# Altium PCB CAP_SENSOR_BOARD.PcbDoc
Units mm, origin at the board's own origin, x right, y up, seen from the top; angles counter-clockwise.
Board outline 114.3 x 63.5 mm, 4 copper layers (Top Layer, GND, PWR, Bottom Layer), stack 1.591 mm thick; 54 components, 40 nets, 232 pads, 121 vias.
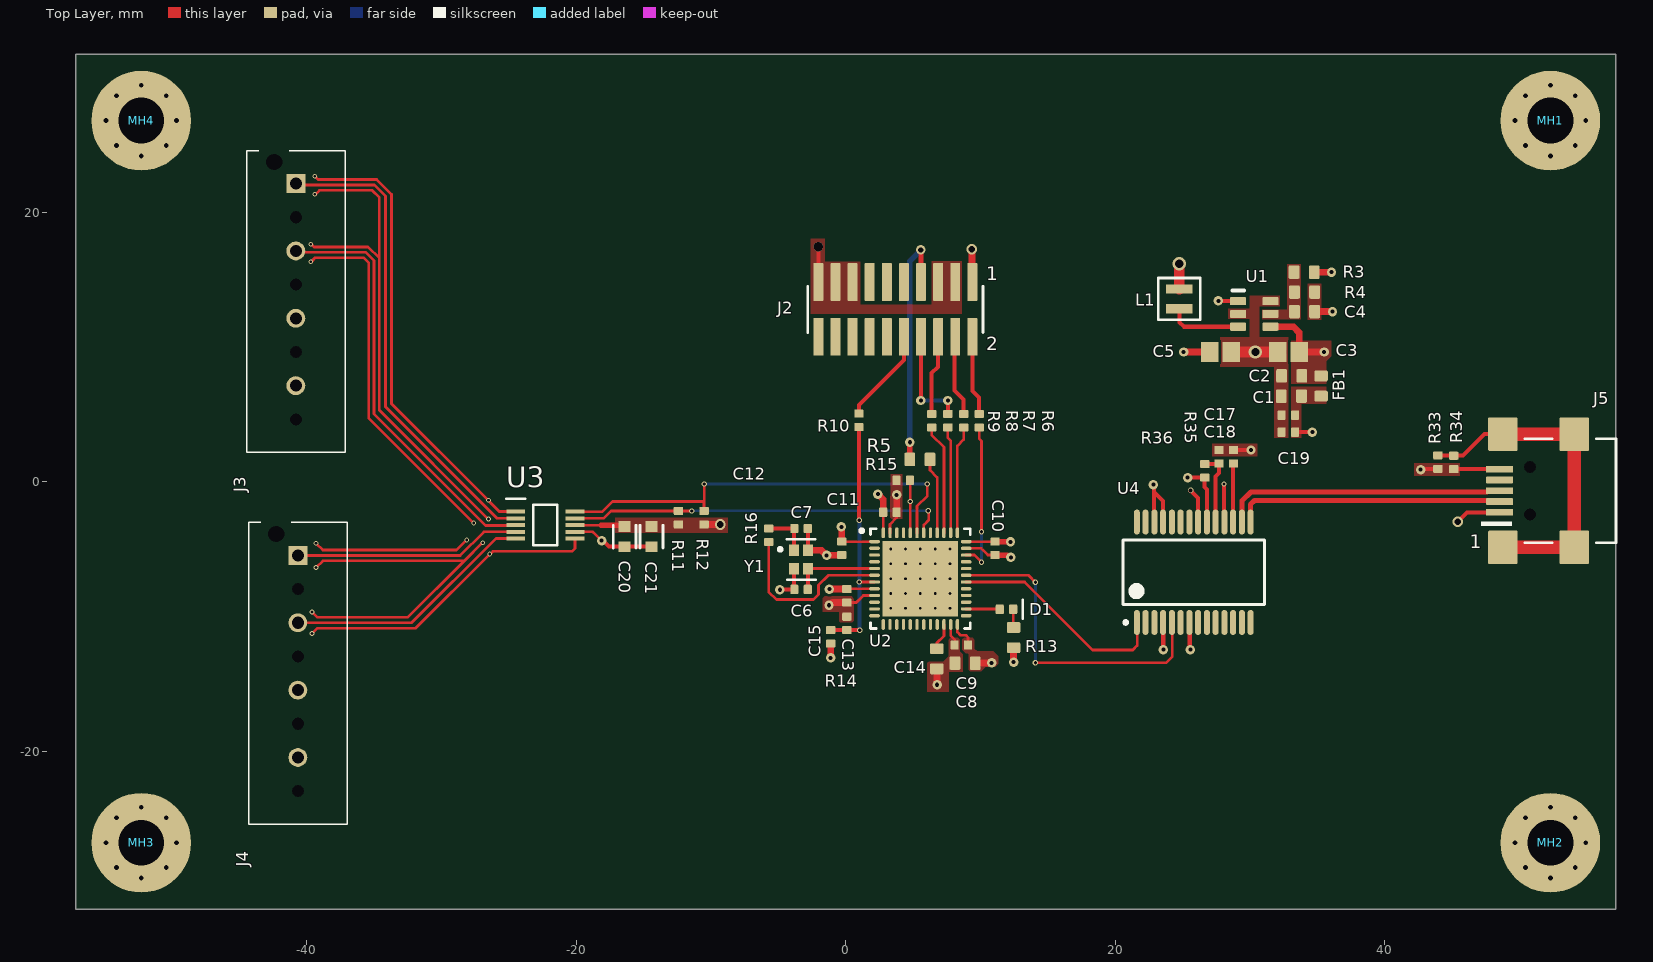
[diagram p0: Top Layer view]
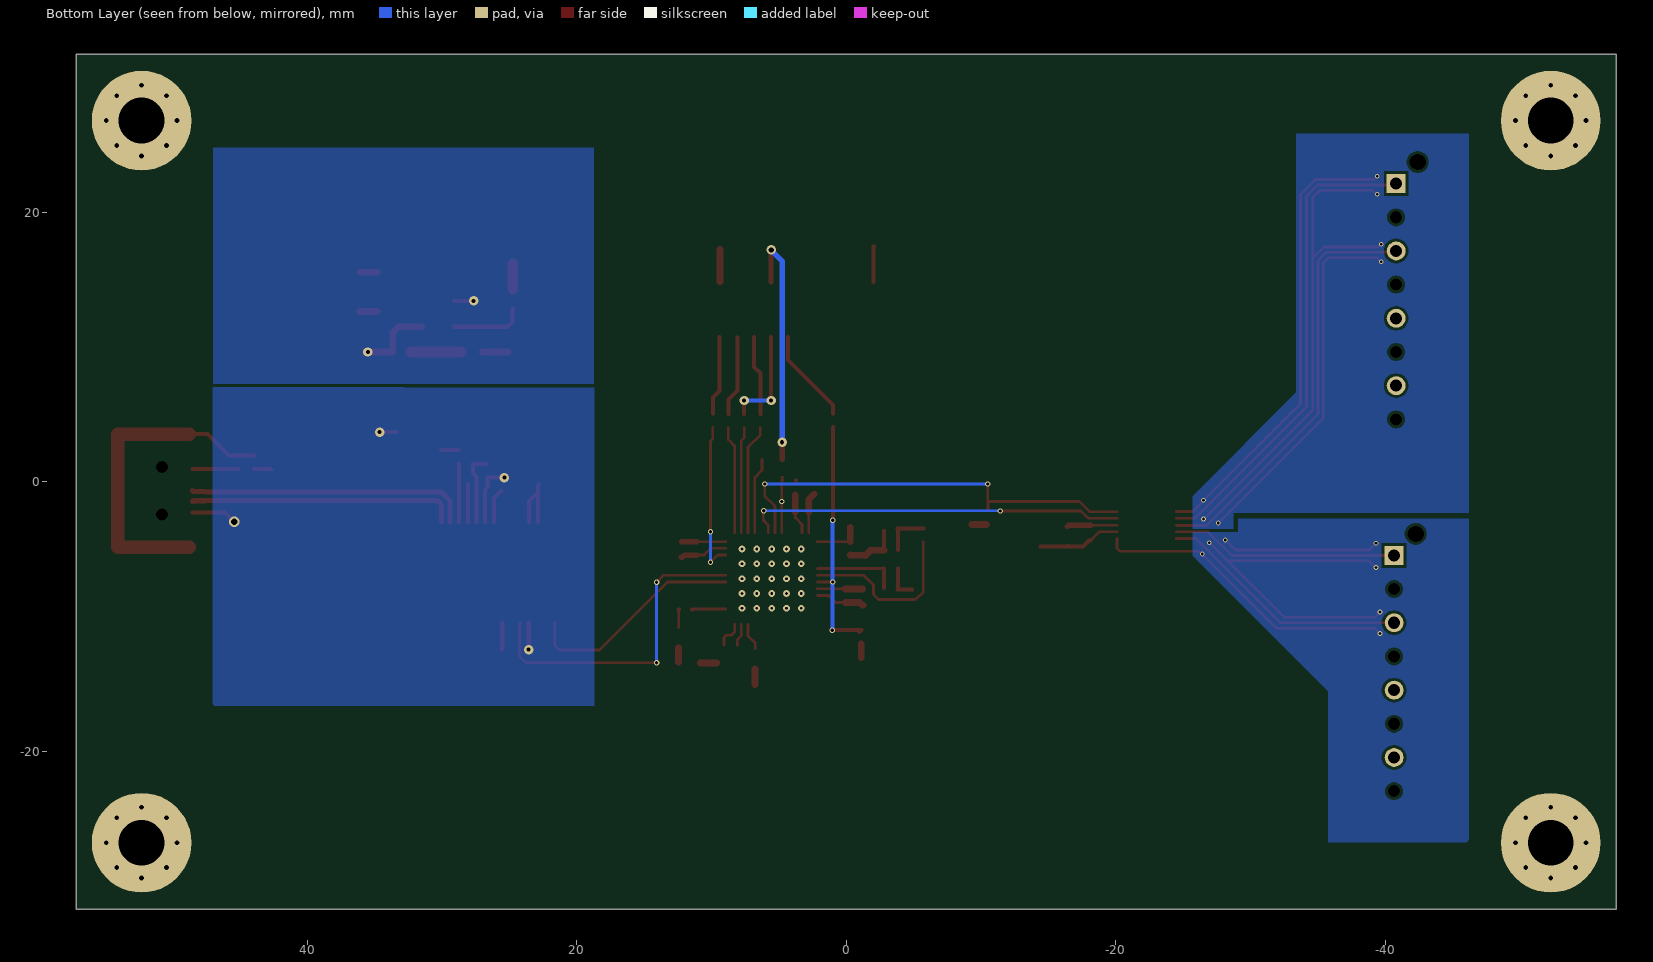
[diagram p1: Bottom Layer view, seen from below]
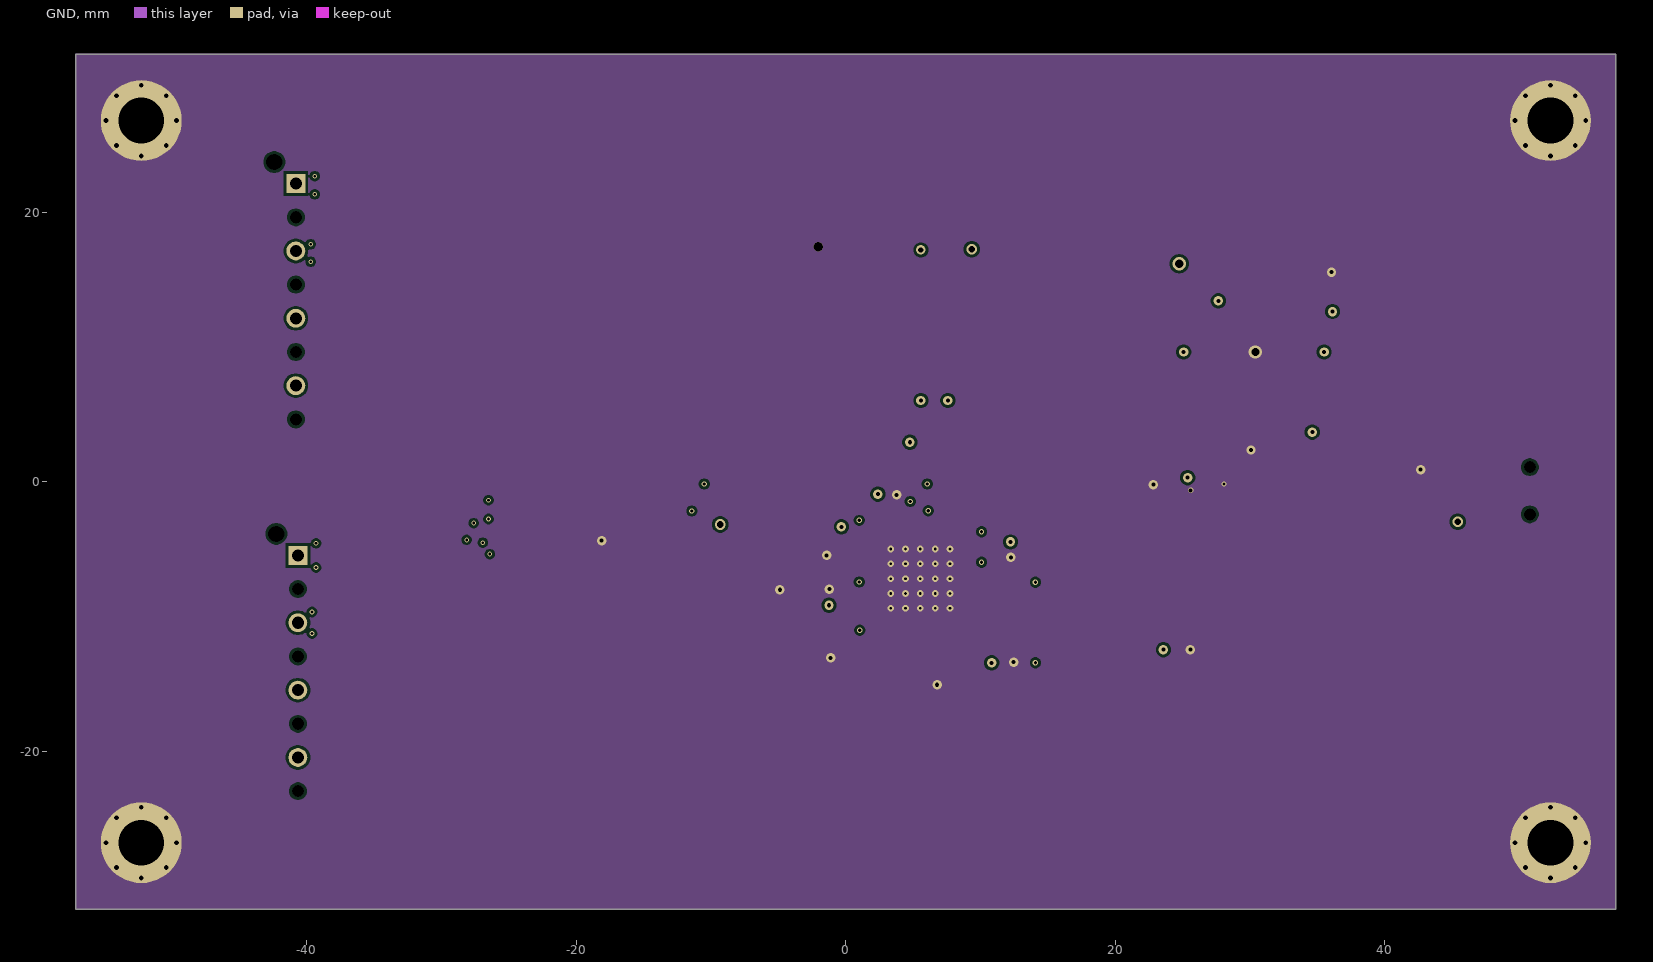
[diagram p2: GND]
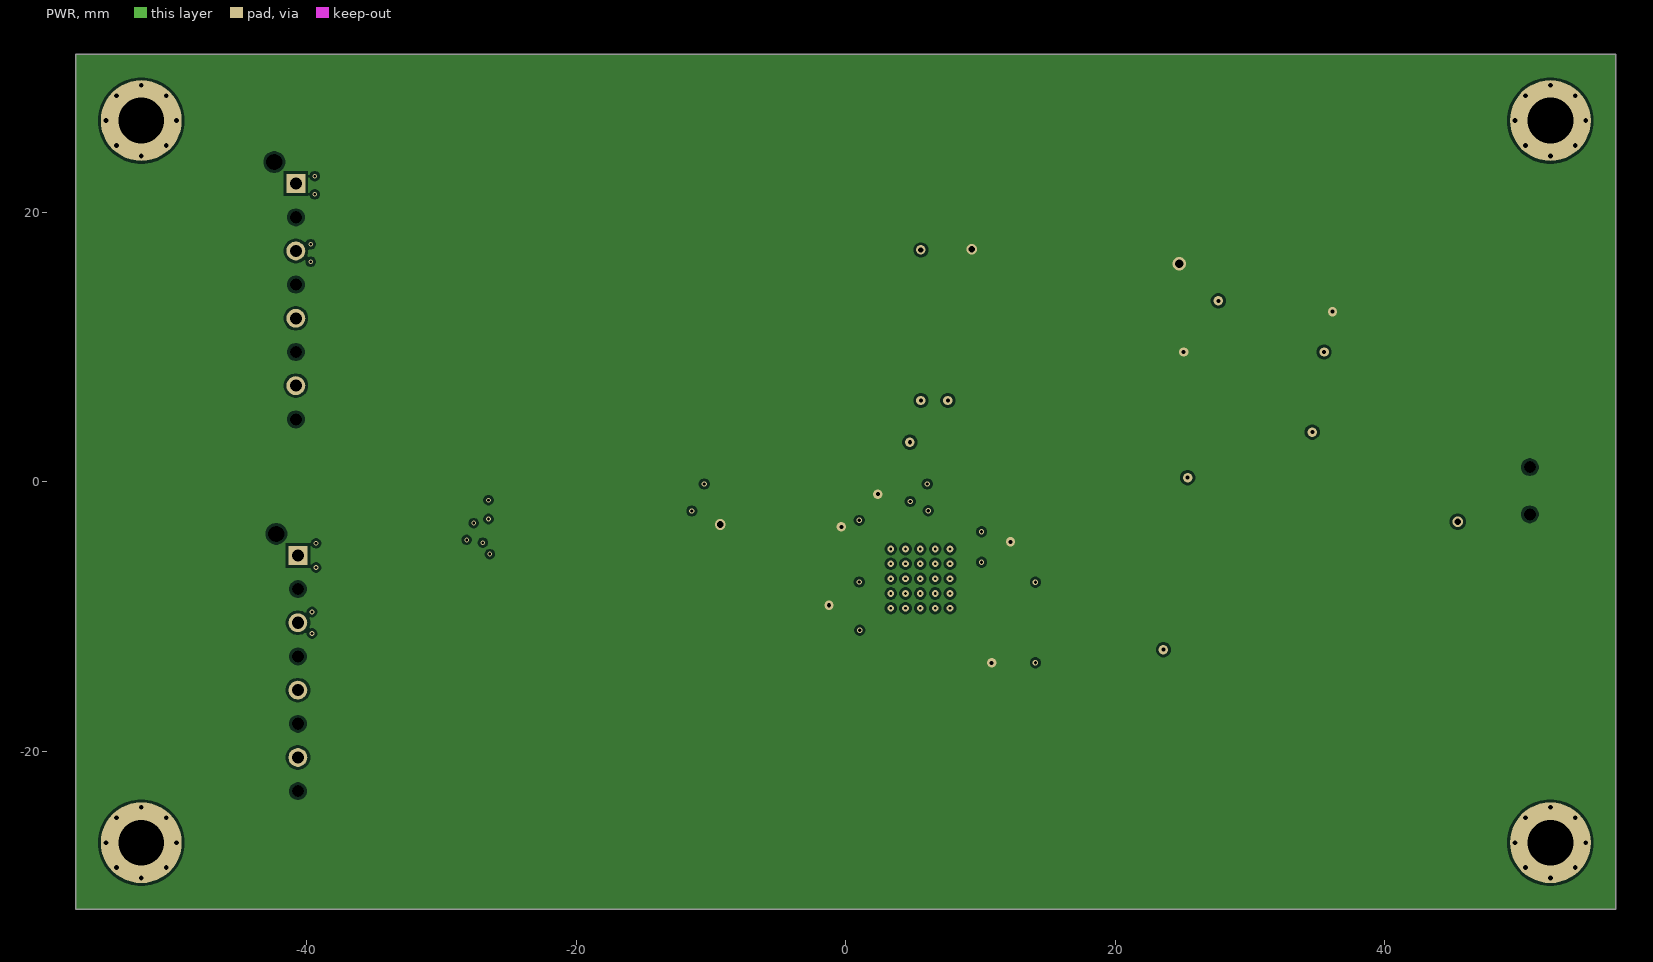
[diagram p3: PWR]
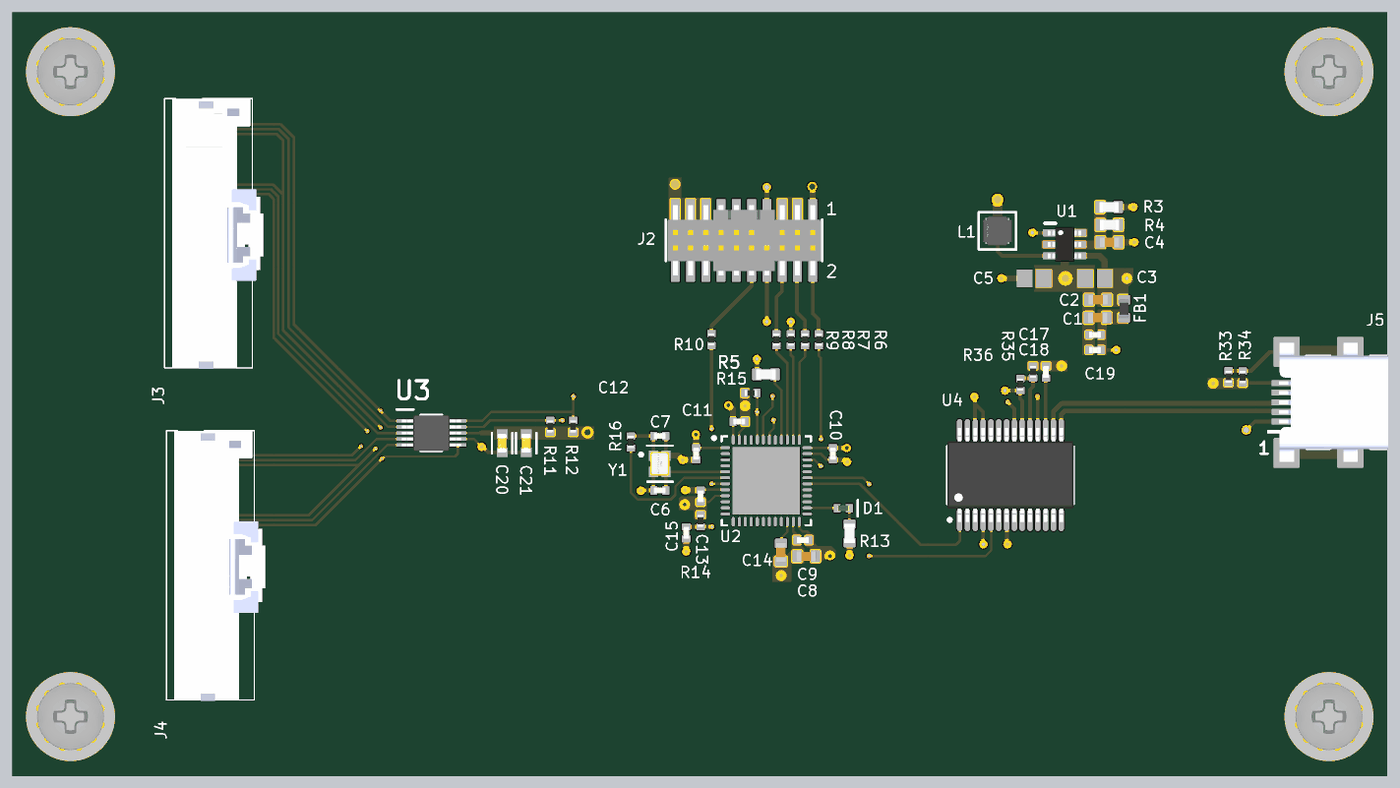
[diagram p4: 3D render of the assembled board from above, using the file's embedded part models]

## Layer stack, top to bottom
Top Solder: solder mask 0.0254, SM-001, Dk 4
Top Layer: signal copper 0.035
Dielectric 1: prepreg 0.2104, PP-7628, Dk 4.4
GND: signal copper 0.0175
Dielectric 3: core 1.065, Core-039, Dk 4.6
PWR: signal copper 0.0175
Dielectric 5: prepreg 0.2104, PP-7628, Dk 4.4
Bottom Layer: signal copper 0.035
Bottom Solder: solder mask 0.0254, SM-001, Dk 4

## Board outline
-57.15,-31.755 -57.15,31.745 57.15,31.745 57.15,-31.755

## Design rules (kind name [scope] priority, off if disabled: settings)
Clearance [All] p1: gap=0.2 ignorepadtopadclearanceinfootprint=FALSE
DiffPairsRouting [All] p1: maxlimit=0.254 minlimit=0.254 mostfreqgap=0.254 toplayer_minwidth=0.381 toplayer_maxwidth=0.381 toplayer_prefwidth=0.381 midlayer1_minwidth=0.381 midlayer1_maxwidth=0.381 midlayer1_prefwidth=0.381 midlayer2_minwidth=0.381 midlayer2_maxwidth=0.381 midlayer2_prefwidth=0.381 bottomlayer_minwidth=0.381 bottomlayer_maxwidth=0.381 bottomlayer_prefwidth=0.381 maxuncoupledlength=12.7
HoleSize [All] p1: absolutevalues=TRUE maxlimit=4 minlimit=0.025 maxpercent=80.000 minpercent=20.000
MinimumSolderMaskSliver [All] p1: minsoldermaskwidth=0.1
PolygonConnect [All] p1: connectstyle=Direct reliefconductorwidth=0.254 reliefentries=4 polygonreliefangle="90 Angle" airgapwidth=0.254
RoutingVias [All] p1: holewidth=0.7 width=0.3 viastyle="Through Hole" minholewidth=0.15 minwidth=0.2 maxholewidth=0.711 maxwidth=1.27
SolderMaskExpansion [All] p1: expansion=0.102 istentingtop=FALSE
UnRoutedNet [All] p1: checkbadconnections=TRUE
Width [All] p1: maxlimit=1 minlimit=0.2 preferedwidth=0.3 midlayer1_maxwidth=1 midlayer2_maxwidth=1 bottomlayer_maxwidth=1 minimp=50.000000 maximp=50.000000 favimp=50.000000
26 further rules are at their usual default settings.

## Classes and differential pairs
component class 5_UART: C17 C18 C19 J5 R33 R34 R35 R36 U4
component class 3_PERIPHERAL: C20 C21 J3 J4 U3
component class 2_MCU: C6 C7 C8 C9 C10 C11 C12 C13 C14 C15 D1 J2 R5 R6 R7 R8 R9 R10 R11 R12 R13 R14 R15 R16 U2 Y1
component class 1_POWER: C1 C2 C3 C4 C5 FB1 L1 MH1 MH2 MH3 MH4 R3 R4 U1
differential pair USB: +USB_P -USB_N

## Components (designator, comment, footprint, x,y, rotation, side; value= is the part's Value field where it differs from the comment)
C1 "100n" CAP_0603 33.075,6.35 r0 top
C2 "100n" CAP_0603 33.1,7.85 r0 top
C3 "4.7uF" CAPC2013X140X50NL20T25 32.85,9.625 r0 top
C4 "22p" CAP_0603 34.05,12.625 r0 top
C5 "4.7uF" CAPC2013X140X50NL20T25 27.8,9.625 r180 top
C6 "6pF" CAP_0402#1 -3.325,-8 r180 top
C7 "6pF" CAP_0402#1 -3.325,-3.475 r0 top
C8 "2.2uF" CAP_0603 8.85,-13.475 r0 top
C9 "100nF" CAP_0402#1 8.575,-12.125 r0 top
C10 "100nF" CAP_0402#1 11.075,-4.95 r90 top
C11 "100nF" CAP_0402#1 3.275,-2.275 r180 top
C12 "100nF" CAP_0402#1 -0.3,-4.95 r90 top
C13 "100nF" CAP_0402#1 0.075,-8.475 r270 top
C14 "2.2uF" CAP_0603 6.75,-13.15 r90 top
C15 "2.2uF" CAP_0402#1 -1.125,-11.525 r90 top
C17 "1uF" CAP_0402#2 32.85,4.937 r180 top
C18 "0.1uF" CAP_0402#2 32.85,3.675 r180 top
C19 "100nF" CAP_0402#1 28.775,1.85 r270 top
C20 "0.1uF" FP-CC0603-DA-MFG -16.425,-4.075 r270 top value="100 nF"
C21 "1uF" FP-CC0603-DA-MFG -14.425,-4.075 r270 top value="1 uF"
D1 "GREEN" LED_0402_GREEN 11.925,-9.475 r0 top
FB1 "120R" FB_0603 35.275,7.1 r90 top
J2 "CN_20P_FTSH-110-01-F-DV-007-K" CN_20P_FTSH-110-01-F-DV-007-K 3.677,12.785 r180 top
J3 "207843-0008" CN_8P_2078430008 -40.825,22.125 r90 top
J4 "207843-0008" CN_8P_2078430008 -40.675,-5.475 r90 top
J5 "CN_5P_USB_UX60-MB-5ST" CN_5P_UX60-MB-5ST 52.675,-0.675 r90 top
L1 "10u" FP-NRH2412-MFG 24.75,13.575 r90 top
MH1 "M3-PTH" MTG_M3_PTH_90317A112 52.3,26.8 r0 top
MH2 "M3-PTH" MTG_M3_PTH_90317A112 52.3,-26.8 r0 top
MH3 "M3-PTH" MTG_M3_PTH_90317A112 -52.3,-26.8 r0 top
MH4 "M3-PTH" MTG_M3_PTH_90317A112 -52.3,26.8 r0 top
R3 "280k" RES_0603 34.025,15.55 r0 top
R4 "887k" RES_0603 34.05,14.075 r0 top
R5 "DNI" RES_0603 5.5,1.65 r0 top
R6 "100R" RES_0402 9.9,4.525 r270 top
R7 "100R" RES_0402 8.75,4.525 r270 top
R8 "100R" RES_0402 6.375,4.525 r270 top
R9 "100R" RES_0402 7.575,4.525 r270 top
R10 "100R" RES_0402 0.975,4.55 r270 top
R11 "2.2K" RES_0402 -12.425,-2.675 r270 top
R12 "2.2k" RES_0402 -10.525,-2.675 r270 top
R13 "1k" RES_0603 12.45,-11.575 r270 top
R14 "10k" RES_0402 0.075,-10.525 r90 top
R15 "10k" RES_0402 4.25,0.1 r0 top
R16 "0R" RES_0402 -5.725,-3.975 r270 top
R33 "0R" RES_0402 43.95,1.45 r90 top
R34 "0R" RES_0402 45.125,1.425 r90 top
R35 "5.1k" RES_0402 26.65,0.8 r270 top
R36 "10k" RES_0402 27.7,1.85 r270 top
U1 "LTC3405ES6#TRMPBF" SOT-23-6 30.32,12.45 r270 top
U2 "STM32F411CEU6" STM-UFQFPN48_L 5.532,-7.199 r0 top
U3 "FDC1004QDGSRQ1" SOP50P490X110-10N -22.3,-3.225 r0 top
U4 "FT232RL" FTDI-SSOP-28_M 25.825,-6.725 r90 top
Y1 "24Mhz" FP-ECX-1637-MFG -3.325,-5.775 r270 top

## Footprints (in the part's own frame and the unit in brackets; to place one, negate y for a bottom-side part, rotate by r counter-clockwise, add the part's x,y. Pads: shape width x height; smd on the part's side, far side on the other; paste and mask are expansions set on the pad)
CAP_0402#1 [mm]
  rrect25% 0.6x0.7 smd: 1(-0.5,0) 2(0.5,0)
  body extent -0.5,-0.26 0.5,0.26, height 0.37
CAP_0402#2 [mm]
  rrect25% 0.6x0.7 smd mask+0.08: 1(-0.5,0) 2(0.5,0)
  body extent -0.5,-0.26 0.5,0.26, height 0.37
CAP_0603 [mm]
  rrect25% 0.8x1 smd: 1(-0.75,0) 2(0.75,0)
  body extent -0.8,-0.4 0.8,0.4, height 0.51
CAPC2013X140X50NL20T25 [mm] "Chip Capacitor, 2-Leads, Body 2.00x1.25mm, IPC Medium Density"
  rect 1.3x1.45 smd mask+0.06: 1(-0.8,0) 2(0.8,0)
  body extent -1.1,-0.72 1.1,0.72, height 1.4
CN_5P_UX60-MB-5ST [mm]
  round 0.5 hole 0.9 unplated paste-2539.97 mask+0.35: 0(-1.75,1.9) 0(1.75,1.9)
  rrect20% 0.5x2 smd paste+0 mask+0: 1(-1.6,4.15) 2(-0.8,4.15) 3(0,4.15) 4(0.8,4.15) 5(1.6,4.15)
  rrect10% 2.5x2.2 smd paste+0 mask+0: 6(-4.2,3.9) 7(4.2,3.9) 8(-4.2,-1.4) 9(4.2,-1.4)
  Top Layer pour cut-out: -3.85,-4.5 -3.85,-2.525 -3.05,-2.525 -3.026,-2.523 -2.981,-2.504 -2.946,-2.469 -2.927,-2.424 -2.925,-2.4 -2.925,-2.4 -2.925,-0.4 -2.927,-0.376 -2.946,-0.331 -2.981,-0.296 -3.026,-0.277 -3.05,-0.275 -3.05,-0.275 -3.85,-0.275 -3.85,1.9 -1.75,1.9 -1.75,3.125 1.75,3.125 1.75,1.9 3.85,1.9 3.85,-0.275 3.05,-0.275 3.026,-0.277 2.981,-0.296 2.946,-0.331 2.927,-0.376 2.925,-0.4 2.925,-0.4 2.925,-2.4 2.927,-2.424 2.946,-2.469 2.981,-2.504 3.026,-2.523 3.05,-2.525 3.05,-2.525 3.85,-2.525 3.85,-4.5
  silkscreen extent -3.85,-4.5 3.85,5.5, body extent -4.95,-4.53 4.95,4.53, height 3.95
CN_8P_2078430008 [mm]
  rect 1.4x1.4 hole 0.9: 1(0,0)
  round 0 hole 0.9: 2(-2.5,0) 4(-7.5,0) 6(-12.5,0) 8(-17.5,0)
  round 1.4 hole 0.9: 3(-5,0) 5(-10,0) 7(-15,0)
  round 0.6 hole 1.2 unplated: MH1(1.6,1.6)
  silkscreen extent -19.95,-3.65 2.45,3.65, body extent -20.01,-4.56 2.44,3.03, height 11.97
CN_20P_FTSH-110-01-F-DV-007-K [mm] "Connector, Header, 20 Pos, 0.05\" Pitch, Vertical, Keyed, SM"
  rrect10% 0.74x2.79 smd: 1(-5.715,-2.035) 2(-5.715,2.035) 3(-4.445,-2.035) 4(-4.445,2.035) 5(-3.175,-2.035) 6(-3.175,2.035) 7(-1.905,-2.035) 8(-1.905,2.035) 9(-0.635,-2.035) 10(-0.635,2.035) 11(0.635,-2.035) 12(0.635,2.035) 13(1.905,-2.035) 14(1.905,2.035) 15(3.175,-2.035) 16(3.175,2.035) 17(4.445,-2.035) 18(4.445,2.035) 19(5.715,-2.035) 20(5.715,2.035)
  silkscreen extent -6.5,-1.72 6.5,1.72, body extent -6.35,-2.92 6.35,2.92, height 6.16
FB_0603 [mm]
  rrect25% 0.8x1 smd: 1(-0.75,0) 2(0.75,0)
  body extent -0.8,-0.4 0.8,0.4, height 0.81
FP-CC0603-DA-MFG [mm]
  rect 0.8x0.9 smd paste+0 mask+0: 1(-0.75,0) 2(0.75,0)
  silkscreen extent -0.85,-0.85 0.85,0.85, body extent -1.35,-0.75 1.35,0.75, height 0.25
FP-ECX-1637-MFG [mm]
  rect 0.85x0.75 smd paste+0 mask+0: 1(-0.675,-0.525) 2(0.675,-0.525) 3(0.675,0.525) 4(-0.675,0.525)
  silkscreen extent -1.5,-1.67 1.5,1.07, body extent -1.2,-1 1.2,1, height 0.25
FP-NRH2412-MFG [mm]
  rect 0.7x2 smd paste+0 mask+0: 1(-0.725,0) 2(0.725,0)
  silkscreen extent -1.55,-1.55 1.55,1.55, body extent -1.35,-1.35 1.35,1.35, height 0.25
FTDI-SSOP-28_M [mm] "SOP, 28-Leads, Body 10.5x5.6mm, Pitch 0.65mm, IPC Low Density"
  oval 1.85x0.45 smd: 1(-3.725,4.225) 2(-3.725,3.575) 3(-3.725,2.925) 4(-3.725,2.275) 5(-3.725,1.625) 6(-3.725,0.975) 7(-3.725,0.325) 8(-3.725,-0.325) 9(-3.725,-0.975) 10(-3.725,-1.625) 11(-3.725,-2.275) 12(-3.725,-2.925) 13(-3.725,-3.575) 14(-3.725,-4.225) 15(3.725,-4.225) 16(3.725,-3.575) 17(3.725,-2.925) 18(3.725,-2.275) 19(3.725,-1.625) 20(3.725,-0.975) 21(3.725,-0.325) 22(3.725,0.325) 23(3.725,0.975) 24(3.725,1.625) 25(3.725,2.275) 26(3.725,2.925) 27(3.725,3.575) 28(3.725,4.225)
  silkscreen extent -3.85,-5.25 2.4,5.25, body extent -3.9,-5.25 3.9,5.25, height 2
LED_0402_GREEN [mm]
  rrect25% 0.6x0.7 smd: A(-0.5,0) K(0.5,0)
  silkscreen extent 1.2,-0.7 1.2,0.7, body extent -0.51,-0.25 0.51,0.25, height 0.45
MTG_M3_PTH_90317A112 [mm] "M3 W INTERNAL TOOTH LOCK WASHER 90317A112"
  round 7.4 / inner round 6 / far side round 7.4 hole 3.404 paste-2539.97 mask+0: 1(0,0)
  body extent -3.7,-3.7 3.7,3.7, height 2.92
RES_0402 [mm]
  rrect25% 0.6x0.7 smd: 1(-0.5,0) 2(0.5,0)
  body extent -0.5,-0.25 0.5,0.25, height 0.3
RES_0603 [mm]
  rrect25% 0.8x1 smd: 1(-0.75,0) 2(0.75,0)
  body extent -0.8,-0.43 0.8,0.43, height 0.52
SOP50P490X110-10N [mm]
  rect 1.4x0.3 smd mask+0.05: 1(-2.2,1) 2(-2.2,0.5) 3(-2.2,0) 4(-2.2,-0.5) 5(-2.2,-1) 6(2.2,-1) 7(2.2,-0.5) 8(2.2,0) 9(2.2,0.5) 10(2.2,1)
  silkscreen extent -2.9,-1.5 0.87,1.95, body extent -2.46,-1.5 2.46,1.5, height 1.1
SOT-23-6 [mm]
  rrect25% 0.6x1.2 smd mask+0.04: 1(-0.95,-1.2) 2(0,-1.2) 3(0.95,-1.2) 4(0.95,1.2) 5(0,1.2) 6(-0.95,1.2)
  silkscreen extent -1.75,-1.63 -1.75,-0.76, body extent -1.45,-1.4 1.45,1.4, height 1.45
STM-UFQFPN48_L [mm] "QFN, 48-Leads, Body 7.1x7.1mm, Pitch 0.5mm, Thermal Pad 5.6x5.6mm, IPC High Density"
  oval 0.8x0.25 smd mask+0.05: 1(-3.4,2.75) 2(-3.4,2.25) 3(-3.4,1.75) 4(-3.4,1.25) 5(-3.4,0.75) 6(-3.4,0.25) 7(-3.4,-0.25) 8(-3.4,-0.75) 9(-3.4,-1.25) 10(-3.4,-1.75) 11(-3.4,-2.25) 12(-3.4,-2.75) 25(3.4,-2.75) 26(3.4,-2.25) 27(3.4,-1.75) 28(3.4,-1.25) 29(3.4,-0.75) 30(3.4,-0.25) 31(3.4,0.25) 32(3.4,0.75) 33(3.4,1.25) 34(3.4,1.75) 35(3.4,2.25) 36(3.4,2.75)
  oval 0.25x0.8 smd mask+0.05: 13(-2.75,-3.4) 14(-2.25,-3.4) 15(-1.75,-3.4) 16(-1.25,-3.4) 17(-0.75,-3.4) 18(-0.25,-3.4) 19(0.25,-3.4) 20(0.75,-3.4) 21(1.25,-3.4) 22(1.75,-3.4) 23(2.25,-3.4) 24(2.75,-3.4) 37(2.75,3.4) 38(2.25,3.4) 39(1.75,3.4) 40(1.25,3.4) 41(0.75,3.4) 42(0.25,3.4) 43(-0.25,3.4) 44(-0.75,3.4) 45(-1.25,3.4) 46(-1.75,3.4) 47(-2.25,3.4) 48(-2.75,3.4)
  rect 5.6x5.6 smd mask+0.05: 49(0,0)
  silkscreen extent -4.47,-3.7 3.7,3.7, body extent -3.55,-3.55 3.55,3.55, height 0.6

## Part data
C1 C2 C4 C8 C14: library part CAP_0603, "Capacitor SMD 0603"
C3 C5: library part CMP-2007-03298-1, Manufacturer=Kemet, Part Number=C0805C475K8RACTU
C6 C7 C9 C10 C11 C12 C13 C15 C17 C18 C19: library part CAP_0402, "Capacitor SMD 0402"
C20: library part CMP-03422-001304-1, "CAP CER 0.1UF 16V X7R 0603", Capacitance="100 nF", Manufacturer=YAGEO, Manufacturer Part Number=CC0603KPX7R7BB104, Package=CC0603-DA, Temperature="-55°C to +125°C", Temperature Characteristic=X7R, Temperature Coefficient=15%, Temperature Range High=+125°C, Temperature Range Low=-55°C, Tolerance=0.1, Voltage="16 V"
C21: library part CMP-03422-000924-1, "CAP CER 1UF 16V X7R 0603", Capacitance="1 uF", Manufacturer=YAGEO, Manufacturer Part Number=CC0603KRX7R7BB105, Package=CC0603-DA, Temperature="-55°C to +125°C", Temperature Characteristic=X7R, Temperature Coefficient=15%, Temperature Range High=+125°C, Temperature Range Low=-55°C, Tolerance=0.1, Voltage="16 V"
D1: library part LED_0402_GREEN, "LED 0402 GREEN SMD"
FB1: library part FB_0603, "Ferrite Bead SMD 0603"
J2: "Connector, Header, 20 Pos, 0.05\" Pitch, Vertical, Keyed, SM", MFR 1="Samtec Inc.", MFR 1 PN=FTSH-110-01-F-DV-007-K, Supplier Part Number 1=SAM11264-ND
J3 J4: "Connector", Manufacturer_Name=Molex
J5: library part CN_5P_UX60-MB-5ST, MFR 1="Hirose Electric Co Ltd", MFR 1 PN=UX60-MB-5ST, Supplier Part Number 1=H2959CT-ND
L1: library part CMP-14484-000582-1, "Shielded Wirewound Inductor 10uH 20% 0.51A 0.72Ω SMD", Case/Package=Nonstandard, Current Rating=450mA, DC Resistance (DCR)=600mR, Inductance=10uH, Max DC Current=810mA, Max Operating Temperature=120°C, Min Operating Temperature=-25°C, Package Quantity=2500, Self Resonant Frequency=29MHz, Test Frequency=100kHz, Tolerance=20%
MH1 MH2 MH3 MH4: library part MTG_M3_PTH_90317A112, "Mounting Screw, M3 x 6mm, Internal Tooth Lock Washer, 90317A112", MFR 1=McMaster-Carr, MFR 1 PN=90317A112
R3 R4 R13: library part RES_0603, "Resistor SMD 0603"
R5: library part RES_0603, "DO NOT INSTALL"
R6 R7 R8 R9 R10 R11 R12 R14 R15 R16 R33 R34 R35 R36: library part RES_0402, "Resistor SMD 0402"
U1: "1.5MHz, 300mA / Synchronous Step-Down / Regulator in ThinSOT", Manufacturer="Analog Devices"
U2: library part CMP-0243-00165-1, "ARM Cortex-M4 32-bit MCU+FPU, 512 KB Flash, 128 KB RAM, 36 I/Os, 48-Pin UFQFPN, -40 to 85 degC, Tray", I/Os (High Current)=36, Operating Frequency(F) (Processor speed) (MHz)=100, Package Description=UFQFPN48, Package Reference="48-Pin Ultra Thin Fine Pitch Quad Flat No-Lead, 7 x 7 x 0.6 mm Body, 0.5 mm Pitch, Exposed Pad", Supply Voltage(Vcc) min (V)=1.7
U3: "Integrated Circuit", Manufacturer_Name="Texas Instruments", Mouser Part Number=595-FDC1004QDGSRQ1
U4: library part CMP-2000-05029-1, "IC USB FS SERIAL UART 28-SSOP", Manufacturer=FTDI, Maximum Operating Temperature=+85degC, Minimum Operating Temperature=-40degC, Package Type=SSOP
Y1: library part CMP-40224-000003-1, "CRYSTAL 24.0000MHZ 8PF SMD", Frequency=24MHz, Load Capacitance=8pF, Manufacturer="ECS Inc.", Manufacturer Part Number=ECS-240-8-37CKM, Package=ECX-1637, Temperature="-20°C to +70°C", Temperature Range High=+70°C, Temperature Range Low=-20°C, Tolerance=10ppm

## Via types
v1: diameter 0.61, hole 0.356, Top Layer to Bottom Layer, 32 vias
v2: diameter 0.5, hole 0.2, Top Layer to Bottom Layer, 25 vias
v3: diameter 0.7, hole 0.3, Top Layer to GND, 14 vias
v4: diameter 0.35, hole 0.2, Top Layer to Bottom Layer, 14 vias
v5: diameter 0.4, hole 0.25, Top Layer to Bottom Layer, 12 vias
v6: diameter 0.7, hole 0.3, Top Layer to Bottom Layer, 8 vias
v7: diameter 0.7, hole 0.3, Top Layer to PWR, 7 vias
v8: diameter 0.8, hole 0.5, Top Layer to PWR, 2 vias
v9: diameter 0.4, hole 0.3, Top Layer to GND, 1 vias
v10: diameter 0.4, hole 0.25, Top Layer to GND, 1 vias
v11: diameter 0.8, hole 0.5, Top Layer to Bottom Layer, 1 vias
v12: diameter 0.7, hole 0.4, Top Layer to Bottom Layer, 1 vias
v13: diameter 0.7, hole 0.7, Top Layer to GND, 1 vias
v14: diameter 1, hole 0.6, Top Layer to PWR, 1 vias
v15: diameter 1, hole 0.6, Top Layer to GND, 1 vias

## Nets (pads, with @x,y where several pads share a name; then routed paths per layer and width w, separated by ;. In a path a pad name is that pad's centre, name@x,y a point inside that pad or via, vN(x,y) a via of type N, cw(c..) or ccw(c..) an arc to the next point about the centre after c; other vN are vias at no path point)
3V3OUT: C19.2 U4.17 | length 4.4
  Top Layer w0.3: U4.17 U4.17@28.775,-2.975 ; U4.17@28.75,-2.975 28.75,1.325 C19.2
+3.3V: C4.2 C5.2 C8.2 C9.2 C10.2 C11.2 C12.2 C13.2 C20.1 C21.1 J2.1 L1.2 R4.2 R11.2 R12.2 R14.2 U2.1 U2.9 U2.24 U2.36 U2.48 U3.8 | length 29.3
  Top Layer w0.2: U3.8 -18.165,-3.225 ; v7(-0.325,-3.35) v7@-0.3,-3.375 ; C12.2 U2.1@2.132,-4.45 ; C13.2 0.775,-8.975 1.301,-8.449 U2.9 ; C11.2 2.779,-2.279 2.779,-3.795 U2.48 ; U2.24 8.282,-11.157 8.525,-11.4 8.913,-11.4 9.075,-11.562 C9.2 ; U2.36@8.932,-4.45 C10.2
  Top Layer w0.3: v8(9.35,17.25) v8@9.371,17.229 ; J2.1@9.371,14.841 J2.1 ; C10.2 C10.2@11.087,-4.462
  Top Layer w0.4: -18.165,-3.225 -16.525,-3.225 C20.1 ; C10.2@11.087,-4.462 12.212,-4.462 v7(12.225,-4.475)
  Top Layer w0.5: R12.2@-10.425,-3.175 v8(-9.325,-3.175) ; v7(-1.25,-9.175) -1.196,-9.175 -0.996,-8.975 C13.2 ; C12.2 v7@-0.3,-3.375 ; v7(2.375,-0.925) 2.775,-1.325 C11.2 ; J2.1@9.371,14.841 v8@9.371,17.229 ; C8.2 9.613,-13.463 10.813,-13.463 v7(10.825,-13.45) ; v7(25.075,9.625) C5.2 ; C4.2 v7(36.125,12.625)
  Top Layer w0.8: L1.2 v14(24.75,16.175)
+5V: C2.2 C3.2 FB1.2 U1.1 U1.4 | length 7.1
  Top Layer w0.3: v6(27.65,13.425) 27.662,13.412 29.107,13.412 U1.1
  Top Layer w0.5: U1.4 33.225,11.5 33.65,11.075 C3.2 v6(35.5,9.625)
CATH_CH_EVEN2: J4.1 U3.4 | length 16.9
  Top Layer w0.2: J4.1 -28.625,-5.475 -26.875,-3.725 U3.4
CATH_CH_EVEN4: J4.3 U3.5 | length 18.8
  Top Layer w0.2: J4.3 -32.225,-10.475 -25.975,-4.225 U3.5
CATH_CH_ODD1: J3.1 U3.2 | length 35.8
  Top Layer w0.2: J3.1 -40.725,22.025 -34.991,22.025 -34.175,21.209 -34.175,5.56 -25.9,-2.715 -24.51,-2.715 U3.2
CATH_CH_ODD3: J3.3 U3.3 | length 31.5
  Top Layer w0.2: J3.3 -40.725,17.025 -35.63,17.025 -35.025,16.42 -35.025,5.025 -26.75,-3.25 -24.525,-3.25 U3.3
CDC_SCL: R11.1 U2.42 U3.9 | length 28.3
  Top Layer w0.2: U3.9 -17.975,-2.725 -17.425,-2.175 R11.1 v5(-11.425,-2.175) ; U2.42 5.792,-3.789 5.792,-3.218 6.154,-2.856 6.154,-2.179 v5(6.125,-2.15)
  Bottom Layer w0.2: v5(-11.425,-2.175) -11.4,-2.15 v5(6.125,-2.15)
CDC_SDA: R12.1 U2.43 U3.10 | length 33
  Top Layer w0.2: U3.10 -18.075,-2.225 -17.325,-1.475 -10.642,-1.475 -10.525,-1.592 R12.1 -10.512,-2.163 -10.512,-0.188 v5(-10.5,-0.175) ; U2.43 5.282,-1.818 6.05,-1.05 v5(6.05,-0.175)
  Bottom Layer w0.2: v5(-10.5,-0.175) v5(6.05,-0.175)
GND: C1.1 C2.1 C3.1 C5.1 C6.2 C7.2 C8.1 C9.1 C10.1 C11.1 C12.1 C13.1 C14.1 C15.1 C17.2 C18.2 C19.1 C20.2 C21.2 J2.3 J2.5 J2.15 J2.17 J2.19 J5.5 MH1.1 MH2.1 MH3.1 MH4.1 R3.2 R13.2 R15.1 R33.1 R34.1 R36.1 U1.2 U1.6 U2.8 U2.23 U2.35 U2.47 U2.49 U3.7 U4.7 U4.18 U4.21 U4.25 U4.26 Y1.2 Y1.4 | length 54.3
  Top Layer w0.2: U3.7 -18.795,-3.725 -18.785,-3.735 -18.765,-3.735 v3(-18.125,-4.375) ; C20.2@-16.475,-4.775 C20.2 ; C13.1 0.101,-7.949 U2.8 ; U2.47 3.282,-3.168 3.775,-2.675 C11.1 ; U2.23 7.782,-11.432 8.075,-11.725 C9.1 ; C9.1@8.05,-12.125 C9.1@8.063,-12.112 ; U2.35 10.049,-4.949 10.175,-5.075 10.542,-5.441 11.066,-5.441 C10.1
  Top Layer w0.3: v3(-18.125,-4.375) -18.017,-4.375 -17.567,-4.825 -16.525,-4.825 C20.2@-16.475,-4.775 ; C20.2 C21.2 ; v3(-4.9,-8.025) -4.875,-8 C6.2@-3.838,-8 ; Y1.2 -3.85,-7.987 C6.2@-3.838,-8 ; C6.2 C6.2@-3.838,-8 ; C7.2@-2.825,-3.675 -2.812,-3.687 -2.812,-5.088 Y1.4 ; v13(-2.05,17.45) -2.044,17.444 -2.044,14.826 J2.19 ; R15.1@3.713,0.088 R15.1@3.725,0.1 ; C14.1 C14.1@6.763,-13.912 ; v3@6.763,-15.062 v3(6.775,-15.075) ; C10.1 C10.1@11.087,-5.462 ; v3(22.825,-0.225) 22.871,-0.271 22.871,-0.771 ; U4.26 22.871,-2.971 22.871,-0.771 ; U4.25 23.55,-1.45 22.871,-0.771 ; U4.7 25.529,-10.479 25.529,-12.429 v3(25.575,-12.475) ; v9(25.6,-0.65) 26.15,-1.2 U4.21 ; v10(28.075,-0.175) 28.088,-0.188 28.088,-2.987 U4.18 ; C19.1 v3(30.075,2.35) ; v3(42.675,0.9) 42.7,0.925 43.925,0.925 R33.1 ; R34.1 J5.5
  Top Layer w0.4: C10.1@11.087,-5.462 11.1,-5.45 11.994,-5.45 12.169,-5.625 v3(12.25,-5.625)
  Top Layer w0.5: Y1.4 -1.81,-5.1 -1.435,-5.475 v3(-1.425,-5.475) -1.412,-5.462 -0.312,-5.462 C12.1 ; v3(-1.225,-7.975) C13.1 ; v3(-1.125,-13.075) C15.1 ; C11.1 v3(3.775,-0.975) ; v3@6.763,-15.062 C14.1@6.763,-13.912 ; v3(12.45,-13.4) R13.2 ; R3.2 v3(36.05,15.55)
  Top Layer w0.8: C5.1 v15(30.396,9.625) C3.1 C3.1@32.3,9.625
  other v1: -52.3,-29.425 52.3,-29.425 -54.15,-28.65 -50.45,-28.65 50.45,-28.65 54.15,-28.65 -54.925,-26.8 -49.675,-26.8 49.675,-26.8 54.925,-26.8 -54.15,-24.95 -50.45,-24.95 50.45,-24.95 54.15,-24.95 -52.3,-24.175 52.3,-24.175 -52.3,24.175 52.3,24.175 -54.15,24.95 -50.45,24.95 50.45,24.95 54.15,24.95 -54.925,26.8 -49.675,26.8 49.675,26.8 54.925,26.8 -54.15,28.65 -50.45,28.65 50.45,28.65 54.15,28.65 -52.3,29.425 52.3,29.425
  other v2: 3.332,-9.399 4.432,-9.399 5.532,-9.399 6.632,-9.399 7.732,-9.399 3.332,-8.299 4.432,-8.299 5.532,-8.299 6.632,-8.299 7.732,-8.299 3.332,-7.199 4.432,-7.199 5.532,-7.199 6.632,-7.199 7.732,-7.199 3.332,-6.099 4.432,-6.099 5.532,-6.099 6.632,-6.099 7.732,-6.099 3.332,-4.999 4.432,-4.999 5.532,-4.999 6.632,-4.999 7.732,-4.999
JTDI: J2.8 R9.1 | length 7.7
  Top Layer w0.3: v6(5.575,6.025) 5.579,6.029 5.579,10.747 J2.8 ; R9.1 v6(7.575,6.025)
  Bottom Layer w0.3: v6(5.575,6.025) v6(7.575,6.025)
JTRST: J2.7 R5.1 | length 18.3
  Top Layer w0.3: v12(5.575,17.2) v12@5.579,17.196 ; J2.7@5.579,14.824 J2.7
  Top Layer w0.4: R5.1 v6(4.75,2.925) ; J2.7@5.579,14.824 v12@5.579,17.196
  Bottom Layer w0.4: v6(4.75,2.925) 4.75,16.375 v12(5.575,17.2)
MCU_BOOT_0: R15.2 U2.44 | length 4
  Top Layer w0.2: R15.2@4.725,0.1 4.775,0.05 v5(4.775,-1.475) 4.782,-1.482 U2.44 ; R15.2@4.725,0.325 R15.2@4.775,0.275
MCU_JTDI: R9.2 U2.38 | length 7.9
  Top Layer w0.2: R9.2 7.575,3.25 7.782,3.043 U2.38
MCU_JTRST: R5.2 U2.40 | length 5.7
  Top Layer w0.2: R5.2 6.25,0.85 6.782,0.318 U2.40
MCU_LED: D1.A U2.26 | length 2.5
  Top Layer w0.2: U2.26 8.942,-9.459 11.409,-9.459 D1.A
MCU_NRST: C15.2 R10.2 R14.1 U2.7 | length 18.5
  Top Layer w0.2: v5(1,-7.449) U2.7
  Top Layer w0.3: C15.2@-0.975,-11.175 C15.2 R14.1 ; R14.1@0.1,-11.025 v5(1.025,-11.025) ; R10.2 0.988,4.037 0.988,-2.863 v5(1,-2.875)
  Bottom Layer w0.3: v5(1,-7.449) v5(1,-2.875) ; v5@1.012,-7.462 1.012,-11.013 v5(1.025,-11.025)
MCU_OSC_IN: C6.1 U2.5 Y1.3 | length 6.4
  Top Layer w0.2: Y1.3 U2.5
  Top Layer w0.3: C6.1@-2.825,-7.875 -2.812,-7.862 -2.812,-6.462 Y1.3 Y1.3
MCU_OSC_OUT: R16.2 U2.6 | length 13
  Top Layer w0.2: R16.2 -5.725,-8.175 -5.15,-8.75 -2.4,-8.75 -2.025,-8.375 -2.025,-7.675 -1.299,-6.949 U2.6
MCU_SWCLK: R7.2 U2.37 | length 8
  Top Layer w0.2: U2.37 8.282,2.657 8.75,3.125 R7.2
MCU_SWDIO: R6.2 U2.34 | length 11.4
  Top Layer w0.2: U2.34 9.549,-5.449 v5(10.075,-5.975) ; R6.2 9.9,3.2 10.075,3.025 v5(10.075,-3.725)
  Bottom Layer w0.2: v5(10.075,-5.975) v5(10.075,-3.725)
MCU_SWO: R8.2 U2.39 | length 8.2
  Top Layer w0.2: R8.2 6.375,3.475 7.282,2.568 U2.39
MCU_USART1_RX: U2.31 U4.5 | length 24.2
  Top Layer w0.2: U2.31 8.942,-6.939 13.539,-6.939 v5(14.075,-7.475) ; v5(14.075,-13.45) 23.775,-13.45 24.225,-13 24.225,-10.475 U4.5
  Bottom Layer w0.2: v5(14.075,-13.45) v5(14.075,-7.475)
MCU_USART1_TX: U2.30 U4.1 | length 16.7
  Top Layer w0.2: U2.30 13.274,-7.449 18.325,-12.5 21.3,-12.5 21.625,-12.175 21.625,-10.475 U4.1
MCU_VCAP1: C14.2 U2.22 | length 2
  Top Layer w0.2: C14.2 6.75,-11.975 7.282,-11.443 U2.22 U2.22@7.272,-10.609
NetD1_K: D1.K R13.1 | length 1.4
  Top Layer w0.2: D1.K 12.425,-10.8 R13.1
  Top Layer w0.3: D1.K D1.K@12.438,-9.487
NRST: J2.10 R10.1 | length 7.1
  Top Layer w0.3: R10.1 0.975,5.675 4.325,9.025 4.325,10.737 J2.10
RESET#: R35.1 R36.2 U4.19 | length 5.5
  Top Layer w0.3: R35.1 26.675,1.325 27.675,1.325 R36.2 27.7,0.65 27.45,0.4 U4.19
SHLD: J5.6 J5.7 J5.8 J5.9 R33.2 R34.2 | length 24.5
  Top Layer w0.3: R33.2 43.962,1.938 45.113,1.938 R34.2 45.8,1.925 47.4,3.525 J5.7
  Top Layer w1: J5.6 J5.8 J5.9 J5.7
SHLD1: U3.1 | length 99.4
  Top Layer w0.2: v4(-39.725,16.325) -39.684,16.325 -39.384,16.625 -35.795,16.625 -35.425,16.255 -35.425,4.725 v4(-27.625,-3.075) ; v4(-39.725,17.625) -39.684,17.625 -39.484,17.425 -35.464,17.425 -34.625,16.586 ; v4(-39.425,21.325) -39.384,21.325 -39.084,21.625 -35.156,21.625 -34.625,21.094 -34.625,16.586 ; v4(-39.425,22.675) -39.175,22.425 -34.825,22.425 -33.725,21.325 -33.725,5.782 v4@-26.497,-1.447 ; v4(-26.525,-2.775) -26.55,-2.775 -34.625,5.3 -34.625,16.586 ; v4@-26.488,-1.455 -25.728,-2.215 -24.51,-2.215 U3.1
  other v4: -26.525,-1.375
SHLD2: U3.6 | length 60.9
  Top Layer w0.2: v4(-39.625,-11.275) -39.612,-11.275 -39.212,-10.875 -31.925,-10.875 v4(-26.425,-5.375) -26.384,-5.375 -26.184,-5.175 -20.325,-5.175 -20.1,-4.95 U3.6 ; v4(-39.625,-9.675) -39.612,-9.675 -39.212,-10.075 -32.525,-10.075 -28.325,-5.875 ; v4(-39.325,-6.375) -38.825,-5.875 -28.325,-5.875 ; v4(-39.325,-4.575) -38.825,-5.075 -28.897,-5.075 -28.15,-4.328 v4(-28.15,-4.325) ; v4(-26.948,-4.527) -26.977,-4.527 -28.325,-5.875
SW: L1.1 U1.3 | length 5.5
  Top Layer w0.3: L1.1 24.775,12.825 24.775,11.825 25.1,11.5 U1.3
SWCLK: J2.4 R7.1 | length 6
  Top Layer w0.2: J2.4@8.075,10.703 J2.4
  Top Layer w0.3: J2.4@8.075,10.703 8.075,6.775 8.75,6.1 R7.1
SWDIO: J2.2 R6.1 | length 5.9
  Top Layer w0.2: R6.1@9.875,5.05 R6.1
  Top Layer w0.3: J2.2 9.392,6.733 9.875,6.25 R6.1@9.875,5.05
SWO: J2.6 R8.1 | length 5.9
  Top Layer w0.2: J2.6@6.825,10.723 J2.6
  Top Layer w0.3: R8.1 6.375,8.075 6.825,8.525 J2.6@6.825,10.723
USB_N: J5.3 U4.16 | length 21
  Top Layer w0.381: U4.16 29.408,-2.992 29.408,-1.421 30.071,-0.757 47.574,-0.757 47.597,-0.734 48.466,-0.734 J5.3
USB_P: J5.2 U4.15 | length 20
  Top Layer w0.381: U4.15 30.043,-2.992 30.043,-1.685 30.335,-1.392 47.574,-1.392 47.597,-1.415 48.466,-1.415 J5.2
USB_PWR: C1.2 C17.1 C18.1 FB1.1 J5.1 R35.2 U4.4 U4.20 | length 11.4
  Top Layer w0.3: U4.4 23.563,-10.462 23.563,-12.462 v6(23.575,-12.475) ; v6(25.375,0.3) R35.2 26.625,0.275 26.625,-0.4 26.8,-0.575 U4.20 ; C18.1 v6(34.625,3.675) ; v11(45.425,-2.975) 46.125,-2.275 J5.1
VFB: C4.1 R3.1 R4.1 U1.5
XTAL_IN: C7.1 R16.1 Y1.1 | length 3.3
  Top Layer w0.3: R16.1 C7.1 ; Y1.1@-3.837,-5.087 C7.1@-3.837,-3.687
pads on no net: J2.9 J2.11 J2.12 J2.13 J2.14 J2.16 J2.18 J2.20 J3.2 J3.4 J3.5 J3.6 J3.7 J3.8 J3.MH1 J4.2 J4.4 J4.5 J4.6 J4.7 J4.8 J4.MH1 J5.0 J5.4 U2.2 U2.3 U2.4 U2.10 U2.11 U2.12 U2.13 U2.14 U2.15 U2.16 U2.17 U2.18 U2.19 U2.20 U2.21 U2.25 U2.27 U2.28 U2.29 U2.32 U2.33 U2.41 U2.45 U2.46 U4.2 U4.3 U4.6 U4.8 U4.9 U4.10 U4.11 U4.12 U4.13 U4.14 U4.22 U4.23 U4.24 U4.27 U4.28

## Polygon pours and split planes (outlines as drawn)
GND on Top Layer "GND_L01_P037" (solid, pour order 37): 27.2,2.8 27.2,1.9 30.55,1.9 30.55,2.8
GND on Top Layer "GND_L01_P035" (solid, pour order 35): 42.2,1.375 42.2,0.425 45.575,0.425 45.575,1.375
USB_PWR on Top Layer "USB_PWR_L01_P034" (solid, pour order 34): 33.025,3.25 33.025,7.05 35.65,7.05 35.65,5.8 33.825,5.8 33.825,3.25
GND on Top Layer "GND_L01_P033" (solid, pour order 33): 32.85,5.925 32.85,3.25 31.8,3.25 31.8,3.975 31.8,4 31.8,5.925
+5V on Top Layer "+5V_L01_P032" (solid, pour order 32): 33.05,10.475 33.05,7.25 35.65,7.25 35.65,8.925 36.025,9.3 36.025,10.475
GND on Top Layer "GND_L01_P031" (solid, pour order 31): 31.8,8.525 31.8,5.925 32.85,5.925 32.85,8.525
GND on Top Layer "GND_L01_P030" (solid, pour order 30): 6.375,16.35 8.6,16.35 8.6,12.45 -2.6,12.45 -2.612,12.462 -2.612,13.15 6.375,13.15
GND on Top Layer "GND_L01_P029" (solid, pour order 29): -2.612,16.135 -2.612,18.013 -2.6,18.025 -1.55,18.025 -1.55,16.135
GND on Top Layer "GND_L01_P028" (solid, pour order 28): -2.612,16.325 -2.612,13.15 1.063,13.15 1.063,16.325
VFB on Top Layer "VFB_L01_P027" (solid, pour order 27): 32.775,14.525 32.775,16.15 33.775,16.15 33.775,14.525
+3.3V on Top Layer "+3.3V_L01_P026" (solid, pour order 26): 34.3,14.675 34.3,12.025 35.3,12.025 35.3,14.675
VFB on Top Layer "VFB_L01_P025" (solid, pour order 25): 30.925,12.775 32.775,12.775 32.775,14.525 33.775,14.525 33.775,12.05 30.925,12.05
GND on Top Layer "GND_L01_P021" (solid, pour order 21): 3.337,0.562 3.312,-2.75 4.2,-2.75 4.2,0.562
GND on Top Layer "GND_L01_P020" (solid, pour order 20): 32.225,13.789 32.225,13.025 30.7,13.025 30.7,13.814 30,13.814 30,12.85 29.975,12.825 30.7,12.825 30.7,13.814
GND on Top Layer "GND_L01_P019" (solid, pour order 19): 28.4,12.825 28.4,12.075 29.975,12.075 29.975,12.825 30.7,12.825 30.7,10.725 29.975,10.725 29.975,12.825
GND on Top Layer "GND_L01_P018" (solid, pour order 18): 27.8,10.725 27.8,8.525 32.85,8.525 32.85,10.725
GND on Top Layer "GND_L01_P010" (solid, pour order 10): 6.05,-15.6 6.05,-13.45 6.15,-13.35 7.25,-13.35 7.625,-12.975 7.625,-11.725 7.75,-11.6 8.3,-11.6 8.45,-11.75 8.45,-12.575 8.675,-12.8 8.675,-14.1 7.625,-14.1 7.625,-14.225 7.625,-14.569 7.625,-15.6
+3.3V on Top Layer "+3.3V_L01_P012" (solid, pour order 12): 8.65,-11.7 8.65,-12.475 8.9,-12.725 9.05,-12.725 9.125,-12.8 9.125,-13.975 9.225,-14.075 10.05,-14.075 10.4,-13.725 11.075,-13.725 11.3,-13.5 11.3,-12.95 10.95,-12.6 9.75,-12.6 9.55,-12.4 9.55,-11.725 9.425,-11.6 8.8,-11.6
+3.3V on Top Layer "+3.3V_L01_P015" (solid, pour order 15): 0.45,-8.5 0.6,-8.725 0.6,-8.8 0.6,-10.325 0.475,-10.45 -0.4,-10.45 -0.5,-10.35 -0.5,-9.65 -1.725,-9.65 -1.725,-8.65 -1.575,-8.5
+3.3V on Top Layer "+3.3V_L01_P014" (solid, pour order 14): -8.775,-2.675 -8.775,-3.775 -17.1,-3.775 -17.1,-2.675 -16.325,-2.675 -16.825,-2.675 -16.325,-2.675
SHLD2 on Bottom Layer "SHLD2_L04_P045" (solid, pour order 45): -25.725,-5.5 -35.75,-15.525 -35.775,-15.525 -35.775,-26.775 -46.05,-26.775 -46.225,-26.6 -46.225,-2.75 -29.1,-2.75 -29.1,-3.75 -25.725,-3.75
SHLD1 on Bottom Layer "SHLD1_L04_P040" (solid, pour order 40): -25.725,-2.3 -25.725,-1.075 -33.425,6.625 -33.425,25.825 -46.225,25.825 -46.225,-2.3
SHLD1 on Bottom Layer "SHLD1_L04_P044" (solid, pour order 44): -28.75,-2.213 -28.75,-3.5 -25.725,-3.5 -25.725,-2.238
+5V on Bottom Layer "+5V_L04_P039" (solid, pour order 39): 18.725,24.794 18.725,17.075 18.725,7.275 35.325,7.275 46.975,7.275 46.975,24.794
USB_PWR on Bottom Layer "USB_PWR_L04_P036" (solid, pour order 36): 18.7,6.987 18.7,-16.625 47.025,-16.625 47.05,-16.6 47.025,-16.575 47.025,7.062
GND on GND "GND_L02_P042" (solid, pour order 42): -57.15,31.75 -57.15,-31.75 57.15,-31.75 57.15,31.75
+3.3V on PWR "+3.3V_L03_P043" (solid, pour order 43): -57.15,31.745 -57.15,-31.75 57.15,-31.75 57.15,31.745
